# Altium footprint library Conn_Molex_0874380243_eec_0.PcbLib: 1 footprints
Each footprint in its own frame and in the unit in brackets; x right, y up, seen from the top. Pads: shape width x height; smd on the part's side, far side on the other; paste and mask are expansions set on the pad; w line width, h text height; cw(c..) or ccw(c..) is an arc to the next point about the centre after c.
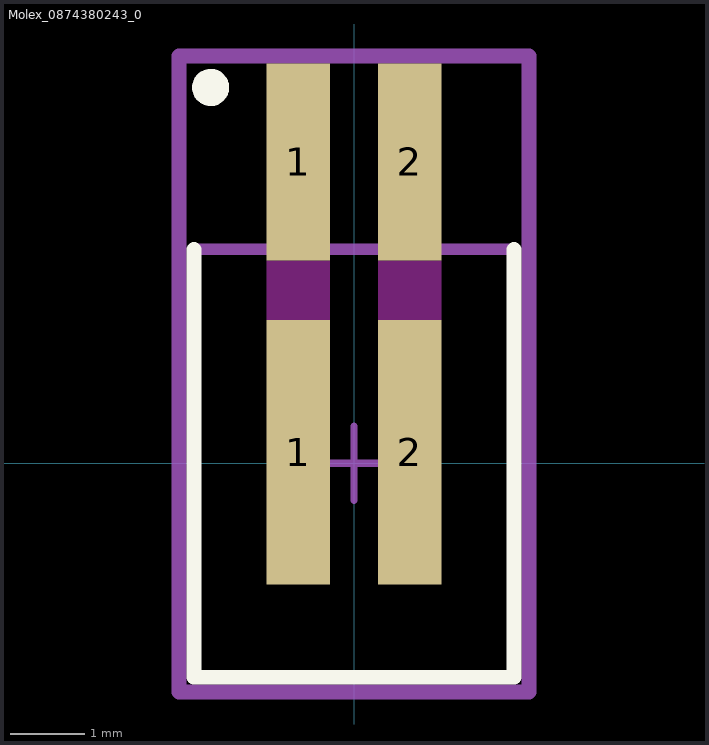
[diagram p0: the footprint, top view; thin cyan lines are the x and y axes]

## Molex_0874380243_0 [mm]
pads (4):
  rect 0.85x3.55 smd paste+0 mask+0: 1(-0.75,0.15) 2(0.75,0.15)
  rect 0.85x2.65 smd paste+0 mask+0: 1(-0.75,4.05) 2(0.75,4.05)
Top Overlay:
  circle w0.25: c-1.926,5.05 r0.125
  lines w0.2: -2.15,2.875 -2.15,-2.875 2.15,-2.875 2.15,2.875
Keep-Out Layer:
  rectangle: -1.175,1.925 -0.325,2.725
  rectangle: 0.325,1.925 1.175,2.725
Mechanical 10:
  lines w0.2: -2.35,-3.075 2.35,-3.075 2.35,5.475 -2.35,5.475 -2.35,-3.075
  text ".Designator" at 0,1.2 h1
Mechanical 12:
  lines w0.152: -2.15,-2.875 2.15,-2.875 2.15,2.875 -2.15,2.875 -2.15,-2.875
Mechanical 15:
  lines w0.1: -0.5,0 0.5,0 ; 0,-0.5 0,0.5
  lines w0.2: -2.35,-3.075 2.35,-3.075 2.35,5.475 -2.35,5.475 -2.35,-3.075
3D body "3dmodel.step": height 0.25, standoff 0, extent -2.35,-3.075 2.35,5.475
